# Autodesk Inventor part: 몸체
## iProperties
Created: 2012-05
Part Number: 몸체
Document SubType Name: 모델링
Designer: SeoGD™
Material: 알루미늄-6061
Mass: 475.546 g
Surface Area: 687.663 cm^2
Volume: 175.478 cm^3
Density: 2.71 g/cm^3
변환 표준: STEP AP214IS
파일 이름: C:\Users\SeoGD\Desktop\?쒗뿕\紐몄껜.stp
전처리기: Build: 253, Release: 2010 SP1 - Date: Wed 07/29/2009
전송 단위: 밀리미터
불확실성: 0.01
Author: SeoGD™
